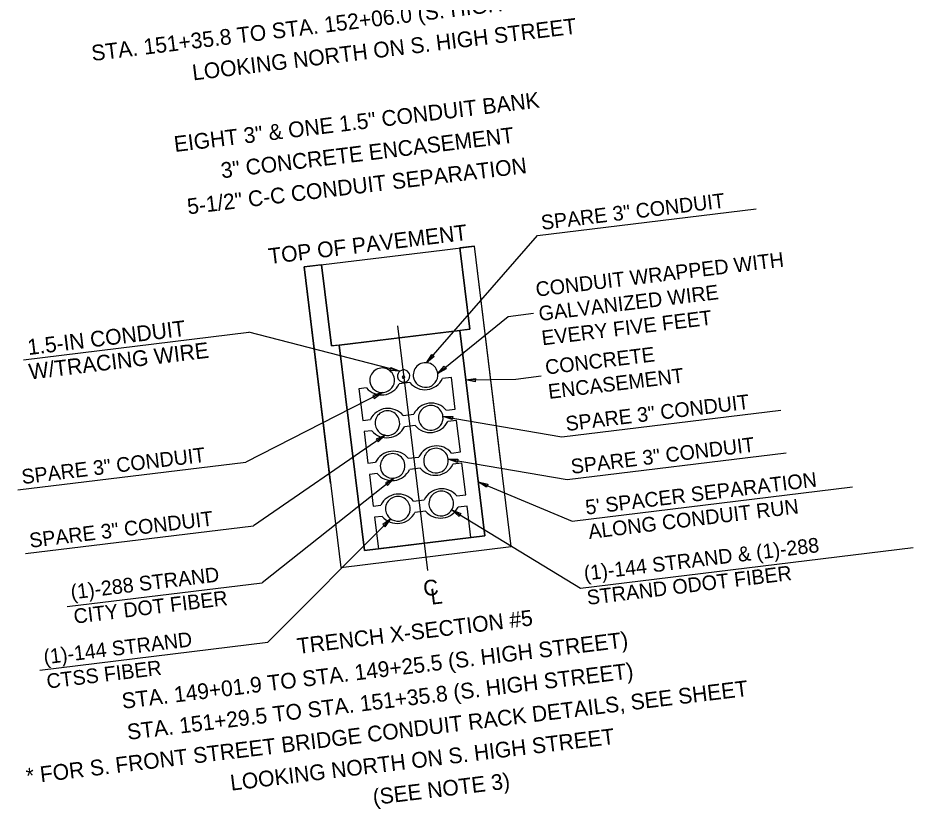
# Model space of a CAD drawing. Extents: x 91401 to 1830080, y 35587 to 712188.
# Drawn here: x 1827050 to 1827391.4, y 711025.8 to 711327.5 of the extents above; entities that cross this region are included whole.
import ezdxf

# ---------------------------------------------------------------- set-up
doc = ezdxf.new("R2010")
doc.units = 0
doc.layers.add('SH_Text', color=7, linetype='Continuous')

msp = doc.modelspace()

# ---------------------------------------------------------------- linework, layer by layer
at = {"layer": 'SH_Text'}
for p, q in [((1827248.16, 711244.49), (1827331.63, 711254.68)), ((1827205.91, 711196.03), (1827248.16, 711244.49)), ((1827224.19, 711240.48), (1827218.6, 711239.8)), ((1827222.38, 711208.84), (1827218.6, 711239.8)), ((1827238.18, 711125.89), (1827224.19, 711240.48)), ((1827165.87, 711233.36), (1827159.16, 711232.54)), ((1827159.16, 711232.54), (1827173.16, 711117.95)), ((1827169.65, 711202.4), (1827165.87, 711233.36)), ((1827210.17, 711191.91), (1827237.04, 711213.7)), ((1827237.04, 711213.7), (1827246.63, 711214.87)), ((1827194.82, 711210.06), (1827206.21, 711116.83)), ((1827052.18, 711197.18), (1827138.17, 711207.67)), ((1827195.67, 711192.75), (1827138.17, 711207.67)), ((1827218.54, 711208.37), (1827228.11, 711129.98)), ((1827172.63, 711202.77), (1827169.65, 711202.4)), ((1827182.2, 711124.38), (1827172.63, 711202.77)), ((1827220.84, 711189.54), (1827239.96, 711189.79)), ((1827220.84, 711189.54), (1827222.69, 711174.4)), ((1827239.96, 711189.79), (1827249.55, 711190.96)), ((1827188.94, 711184.62), (1827136.95, 711158.14)), ((1827221.68, 711182.7), (1827224.2, 711162.05)), ((1827257.53, 711167.75), (1827341, 711177.95)), ((1827212.17, 711175.57), (1827257.53, 711167.75)), ((1827190.05, 711168.37), (1827139.92, 711133.86)), ((1827259.53, 711151.42), (1827342.99, 711161.62)), ((1827050.05, 711147.53), (1827136.95, 711158.14)), ((1827214.16, 711159.24), (1827259.53, 711151.42)), ((1827193.53, 711151.99), (1827143.17, 711112.11)), ((1827225.6, 711150.57), (1827261.45, 711135.64)), ((1827261.45, 711135.64), (1827368.4, 711148.69)), ((1827215.49, 711139.86), (1827264.58, 711110.05)), ((1827053.01, 711123.25), (1827139.92, 711133.86)), ((1827192.26, 711136.46), (1827145.34, 711089.41)), ((1827228.11, 711129.98), (1827182.2, 711124.38)), ((1827173.16, 711117.95), (1827238.18, 711125.89)), ((1827264.58, 711110.05), (1827391.45, 711125.54)), ((1827068.83, 711103.03), (1827143.17, 711112.11)), ((1827058.44, 711078.79), (1827145.34, 711089.41))]:
    msp.add_line(p, q, dxfattribs=at)
for points in [[(1827159.16, 711232.54), (1827211.9, 711238.98), (1827224.19, 711240.48), (1827224.19, 711240.48)], [(1827165.87, 711233.36), (1827169.65, 711202.4), (1827222.38, 711208.84), (1827218.6, 711239.8)], [(1827218.6, 711239.8), (1827222.38, 711208.84), (1827218.54, 711208.37)], [(1827234.27, 711157.96), (1827224.19, 711240.48)], [(1827169.24, 711150.02), (1827159.16, 711232.54)], [(1827172.63, 711202.77), (1827195.38, 711205.54), (1827218.54, 711208.37), (1827224.2, 711162.05)], [(1827172.63, 711202.77), (1827213.19, 711207.72), (1827218.54, 711208.37), (1827224.2, 711162.05)], [(1827172.63, 711202.77), (1827195.38, 711205.54), (1827218.54, 711208.37), (1827224.2, 711162.05)], [(1827178.29, 711156.45), (1827172.63, 711202.77)], [(1827178.29, 711156.45), (1827172.63, 711202.77)], [(1827199.52, 711188.44), (1827195.47, 711187.94)], [(1827213.44, 711177.92), (1827216.83, 711178.34), (1827215.36, 711190.37), (1827211.97, 711189.96)], [(1827183.02, 711186.42), (1827180.09, 711186.07), (1827181.56, 711174.03)], [(1827181.56, 711174.03), (1827184.49, 711174.39)], [(1827196.94, 711175.91), (1827200.99, 711176.4)], [(1827201.51, 711172.1), (1827197.46, 711171.6)], [(1827215.44, 711161.58), (1827218.82, 711162), (1827217.35, 711174.03), (1827213.97, 711173.62)], [(1827185.01, 711170.08), (1827182.09, 711169.73), (1827183.56, 711157.69)], [(1827183.56, 711157.69), (1827186.48, 711158.05)], [(1827198.93, 711159.57), (1827202.98, 711160.06)], [(1827217.43, 711145.25), (1827220.82, 711145.66), (1827219.35, 711157.7), (1827215.96, 711157.29)], [(1827203.51, 711155.77), (1827199.46, 711155.27)], [(1827187.01, 711153.75), (1827184.08, 711153.4), (1827185.55, 711141.36)], [(1827200.93, 711143.24), (1827204.98, 711143.73)], [(1827185.55, 711141.36), (1827188.47, 711141.72)], [(1827187.54, 711125.03), (1827222.81, 711129.33), (1827221.34, 711141.37), (1827217.95, 711140.96)], [(1827189, 711137.42), (1827186.07, 711137.07), (1827187.54, 711125.03)], [(1827205.5, 711139.44), (1827201.45, 711138.94)]]:
    msp.add_lwpolyline(points, dxfattribs=at)
for points in [[(1827182.2, 711124.38), (1827228.11, 711129.98), (1827218.54, 711208.37), (1827172.63, 711202.77)], [(1827207.86, 711199.19), (1827208.78, 711198.39), (1827205.91, 711196.03)], [(1827191.97, 711193.08), (1827192.27, 711194.26), (1827195.67, 711192.75)], [(1827212.64, 711194.69), (1827213.41, 711193.74), (1827210.17, 711191.91)], [(1827224.53, 711189.99), (1827224.48, 711188.77), (1827220.84, 711189.54)], [(1827185.4, 711183.5), (1827185.95, 711182.41), (1827188.94, 711184.62)], [(1827215.89, 711175.55), (1827215.68, 711174.35), (1827212.17, 711175.57)], [(1827186.69, 711166.8), (1827187.38, 711165.79), (1827190.05, 711168.37)], [(1827217.88, 711159.22), (1827217.67, 711158.02), (1827214.16, 711159.24)], [(1827190.27, 711150.19), (1827191.03, 711149.23), (1827193.53, 711151.99)], [(1827229.21, 711149.68), (1827228.72, 711148.55), (1827225.6, 711150.57)], [(1827218.93, 711138.46), (1827218.29, 711137.42), (1827215.49, 711139.86)], [(1827189.22, 711134.32), (1827190.08, 711133.45), (1827192.26, 711136.46)]]:
    msp.add_lwpolyline(points, close=True, dxfattribs=at)
for centre, radius, start, end in [((1827205.51, 711191.34), 4.7, 6.9614, 186.9614), ((1827188.97, 711189.32), 4.7, 6.9614, 186.9614), ((1827197.17, 711190.93), 2.35, 6.9614, 186.9614), ((1827205.51, 711191.34), 4.7, 186.9614, 6.9614), ((1827188.75, 711191.18), 7.45, 219.6485, 334.2743), ((1827188.97, 711189.32), 4.7, 186.9614, 6.9614), ((1827197.17, 711190.93), 2.35, 186.9614, 6.9614), ((1827197.14, 711190.52), 0.5, 6.9614, 186.9614), ((1827197.14, 711190.52), 0.5, 186.9614, 6.9614), ((1827205.26, 711193.19), 7.45, 219.6485, 334.2743), ((1827191.2, 711171.15), 7.45, 39.6485, 154.2743), ((1827190.96, 711172.98), 4.7, 6.9614, 186.9614), ((1827207.7, 711173.17), 7.45, 39.6485, 154.2743), ((1827207.5, 711175), 4.7, 6.9614, 186.9614), ((1827207.5, 711175), 4.7, 186.9614, 6.9614), ((1827190.75, 711174.84), 7.45, 219.6485, 334.2743), ((1827190.96, 711172.98), 4.7, 186.9614, 6.9614), ((1827207.25, 711176.85), 7.45, 219.6485, 334.2743), ((1827209.7, 711156.83), 7.45, 39.6485, 154.2743), ((1827193.19, 711154.81), 7.45, 39.6485, 154.2743), ((1827192.96, 711156.65), 4.7, 6.9614, 186.9614), ((1827209.5, 711158.67), 4.7, 6.9614, 186.9614), ((1827192.96, 711156.65), 4.7, 186.9614, 6.9614), ((1827209.25, 711160.52), 7.45, 219.6485, 334.2743), ((1827209.5, 711158.67), 4.7, 186.9614, 6.9614), ((1827192.74, 711158.51), 7.45, 219.6485, 334.2743), ((1827211.69, 711140.5), 7.45, 39.6485, 154.2743), ((1827211.49, 711142.33), 4.7, 6.9614, 186.9614), ((1827195.19, 711138.48), 7.45, 39.6485, 154.2743), ((1827194.95, 711140.31), 4.7, 6.9614, 186.9614), ((1827194.95, 711140.31), 4.7, 186.9614, 6.9614), ((1827211.24, 711144.19), 7.45, 219.6485, 334.2743), ((1827211.49, 711142.33), 4.7, 186.9614, 6.9614), ((1827194.74, 711142.18), 7.45, 219.6485, 334.2743)]:
    msp.add_arc(centre, radius, start, end, dxfattribs=at)

# ---------------------------------------------------------------- texts
for s, height, p in [('STA. 151+35.8 TO STA. 152+06.0 (S. HIGH STREET)', 6, (1827078.44, 711311.07)), ('LOOKING NORTH ON S. HIGH STREET', 6, (1827116.91, 711303.68)), ('EIGHT 3" & ONE 1.5" CONDUIT BANK', 6, (1827109.95, 711276.38)), ('3" CONCRETE ENCASEMENT', 6, (1827127.82, 711266.34)), ('5-1/2" C-C CONDUIT SEPARATION', 6, (1827114.99, 711252.58)), ('SPARE 3" CONDUIT', 5.6, (1827249.9, 711246.66)), ('TOP OF PAVEMENT', 6, (1827145.97, 711233.63)), ('CONDUIT WRAPPED WITH', 5.6, (1827247.86, 711221.17)), ('GALVANIZED WIRE', 5.6, (1827248.99, 711211.91)), ('EVERY FIVE FEET', 5.6, (1827250.12, 711202.64)), ('1.5-IN CONDUIT', 6, (1827054.06, 711198.93)), ('W/TRACING WIRE', 6, (1827054.57, 711189.58)), ('CONCRETE ', 5.6, (1827251.49, 711191.47)), ('ENCASEMENT', 5.6, (1827252.62, 711182.2)), ('SPARE 3" CONDUIT', 5.6, (1827259.27, 711169.93)), ('SPARE 3" CONDUIT', 5.6, (1827261.27, 711153.6)), ('SPARE 3" CONDUIT', 5.6, (1827051.79, 711149.7)), ("5' SPACER SEPARATION ", 5.6, (1827266.81, 711138.05)), ('ALONG CONDUIT RUN', 5.6, (1827267.94, 711128.78)), ('SPARE 3" CONDUIT', 5.6, (1827054.76, 711125.42)), ('(1)-144 STRAND & (1)-288 ', 5.6, (1827266.24, 711112.89)), ('(1)-288 STRAND ', 5.6, (1827070.51, 711105.71)), ('STRAND ODOT FIBER', 5.6, (1827267.37, 711103.63)), ('C', 6, (1827205, 711106.89)), ('L', 6, (1827207.75, 711103.71)), ('CITY DOT FIBER', 5.6, (1827071.64, 711096.45)), ('TRENCH X-SECTION #5', 6, (1827156.85, 711084.92)), ('(1)-144 STRAND', 5.6, (1827060.18, 711080.97)), ('STA. 149+01.9 TO STA. 149+25.5 (S. HIGH STREET)', 6, (1827090.04, 711063.99)), ('CTSS FIBER', 5.6, (1827061.32, 711071.7)), ('STA. 151+29.5 TO STA. 151+35.8 (S. HIGH STREET)', 6, (1827092.06, 711052.15)), ('* FOR S. FRONT STREET BRIDGE CONDUIT RACK DETAILS, SEE SHEET', 6, (1827053.53, 711035.36)), ('LOOKING NORTH ON S. HIGH STREET', 6, (1827131.41, 711032.78)), ('(SEE NOTE 3)', 6, (1827185.76, 711027.32))]:
    msp.add_text(s, height=height, rotation=6.9614, dxfattribs=at).set_placement(p)

doc.saveas('drawing.dxf')
